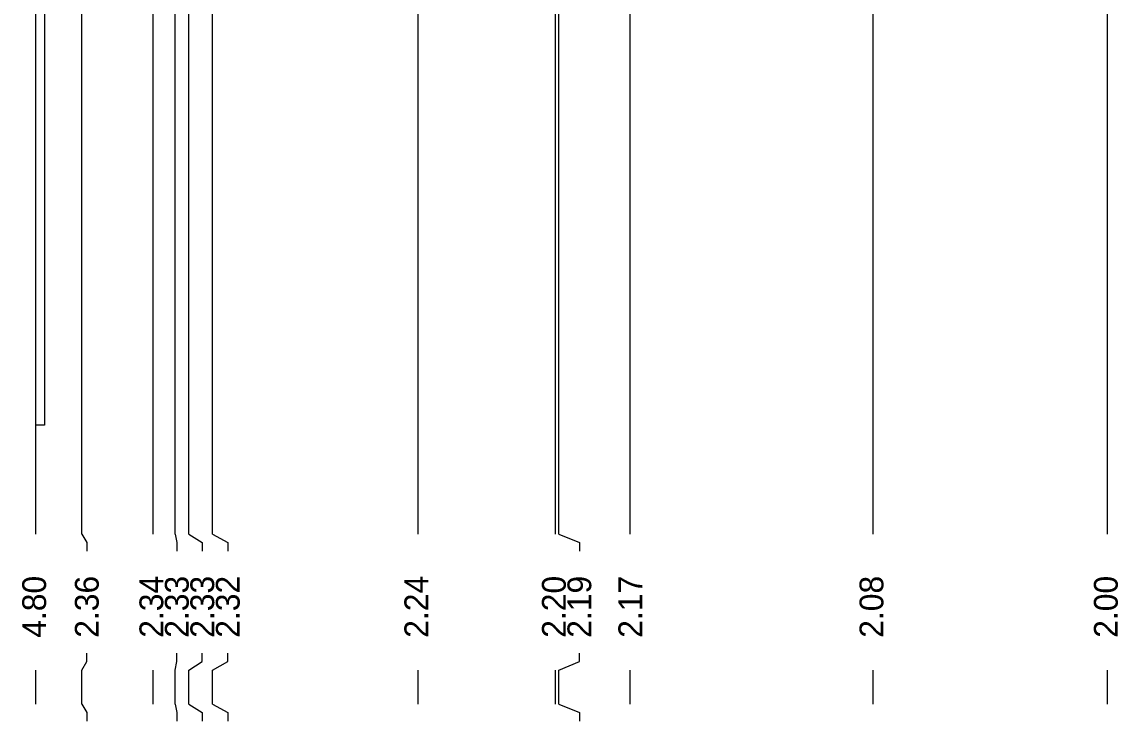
# Model space of a CAD drawing. Extents: x -760612 to 2731, y -975740 to 2995.
# Drawn here: x -361 to 284, y 1510 to 1921 of the extents above; entities that cross this region are included whole.
import ezdxf

# ---------------------------------------------------------------- set-up
doc = ezdxf.new("R2010")
doc.units = 0
for name, color, linetype in [('Implicitní', 7, 'Continuous'), ('INVESTICE', 7, 'Continuous'), ('SACHTY', 7, 'Continuous')]:
    doc.layers.add(name, color=color, linetype=linetype)

msp = doc.modelspace()

# ---------------------------------------------------------------- linework, layer by layer
at = {"layer": 'Implicitní'}
for p, q in [((-353.01, 1619.88), (-353.01, 2163.88)), ((-249.01, 1619.88), (-249.01, 2163.88)), ((-128.01, 1619.88), (-128.01, 2163.88)), ((-47.01, 1619.88), (-47.01, 2163.88)), ((139.99, 1619.88), (139.99, 2163.88)), ((277.99, 1619.88), (277.99, 2163.88)), ((-249.01, 1619.88), (-240.01, 1614.88)), ((-240.01, 1614.88), (-240.01, 1609.88)), ((-240.01, 1544.88), (-240.01, 1549.88)), ((-249.01, 1539.88), (-240.01, 1544.88)), ((-353.01, 1519.88), (-353.01, 1539.88)), ((-249.01, 1519.88), (-249.01, 1539.88)), ((-128.01, 1519.88), (-128.01, 1539.88)), ((-47.01, 1519.88), (-47.01, 1539.88)), ((139.99, 1519.88), (139.99, 1539.88)), ((277.99, 1519.88), (277.99, 1539.88)), ((-249.01, 1519.88), (-240.01, 1514.88)), ((-240.01, 1514.88), (-240.01, 1509.88))]:
    msp.add_line(p, q, dxfattribs=at)
at = {"layer": 'INVESTICE'}
for p, q in [((-326.01, 1619.88), (-326.01, 2163.88)), ((-284.01, 1619.88), (-284.01, 2163.88)), ((-271.01, 1619.88), (-271.01, 2163.88)), ((-263.01, 1619.88), (-263.01, 2163.88)), ((-45.01, 1619.88), (-45.01, 2163.88)), ((-3.01, 1619.88), (-3.01, 2163.88)), ((-326.01, 1619.88), (-323.01, 1614.88)), ((-323.01, 1614.88), (-323.01, 1609.88)), ((-271.01, 1619.88), (-270.01, 1614.88)), ((-270.01, 1614.88), (-270.01, 1609.88)), ((-263.01, 1619.88), (-255.01, 1614.88)), ((-255.01, 1614.88), (-255.01, 1609.88)), ((-45.01, 1619.88), (-33.01, 1614.88)), ((-33.01, 1614.88), (-33.01, 1609.88)), ((-323.01, 1544.88), (-323.01, 1549.88)), ((-270.01, 1544.88), (-270.01, 1549.88)), ((-255.01, 1544.88), (-255.01, 1549.88)), ((-33.01, 1544.88), (-33.01, 1549.88)), ((-326.01, 1539.88), (-323.01, 1544.88)), ((-271.01, 1539.88), (-270.01, 1544.88)), ((-263.01, 1539.88), (-255.01, 1544.88)), ((-45.01, 1539.88), (-33.01, 1544.88)), ((-326.01, 1519.88), (-326.01, 1539.88)), ((-284.01, 1519.88), (-284.01, 1539.88)), ((-271.01, 1519.88), (-271.01, 1539.88)), ((-263.01, 1519.88), (-263.01, 1539.88)), ((-45.01, 1519.88), (-45.01, 1539.88)), ((-3.01, 1519.88), (-3.01, 1539.88)), ((-326.01, 1519.88), (-323.01, 1514.88)), ((-271.01, 1519.88), (-270.01, 1514.88)), ((-263.01, 1519.88), (-255.01, 1514.88)), ((-45.01, 1519.88), (-33.01, 1514.88)), ((-323.01, 1514.88), (-323.01, 1509.88)), ((-270.01, 1514.88), (-270.01, 1509.88)), ((-255.01, 1514.88), (-255.01, 1509.88)), ((-33.01, 1514.88), (-33.01, 1509.88))]:
    msp.add_line(p, q, dxfattribs=at)
at = {"layer": 'SACHTY'}
msp.add_lwpolyline([(-348.01, 1946.88), (-348.01, 1683.88), (-353.01, 1683.88)], dxfattribs=at)

# ---------------------------------------------------------------- texts
at = {"layer": 'Implicitní'}
for s, p in [('4.80', (-347.01, 1558.88)), ('2.32', (-233.01, 1558.88)), ('2.24', (-122.01, 1558.88)), ('2.20', (-41.01, 1558.88)), ('2.08', (145.99, 1558.88)), ('2.00', (283.99, 1558.88))]:
    msp.add_text(s, height=14, rotation=90, dxfattribs=at).set_placement(p)
at = {"layer": 'INVESTICE'}
for s, p in [('2.36', (-316.01, 1558.88)), ('2.34', (-278.01, 1558.88)), ('2.33', (-263.01, 1558.88)), ('2.33', (-248.01, 1558.88)), ('2.19', (-26.01, 1558.88)), ('2.17', (3.99, 1558.88))]:
    msp.add_text(s, height=14, rotation=90, dxfattribs=at).set_placement(p)

doc.saveas('drawing.dxf')
